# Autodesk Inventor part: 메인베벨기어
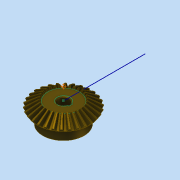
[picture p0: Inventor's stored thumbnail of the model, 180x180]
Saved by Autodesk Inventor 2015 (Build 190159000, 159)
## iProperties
Created: 2018-09
Part Number: 메인베벨기어
Material: 강철, 탄소
Document SubType Name: Modeling
Categories: <?xml version="1.0" encoding="UTF-16"?> <MemberInstance><Categories><FamilyTemplate><FamilyTemplateParameter ValueType="xs:double" Id="1" ObjectReferenceKey="da
Mass: 290.333 g
Surface Area: 107.709 cm^2
Volume: 36.8911 cm^3
Density: 7.87 g/cm^3
Appearance: 얼룩무늬
CustomPartVersion: 1
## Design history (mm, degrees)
node "맨 위 점"
node "메쉬 평면2"
sketch "톱니 본체 스케치"
  geometry: L1 (0, 0)-(28.669, -21.997); L2 (28.669, -21.997)-(31.109, -18.336); L3 (31.109, -18.336)-(0, 0); L4 (30, -20)-(0, 0); L5 (17.219, -13.212)-(18.685, -11.013); L6 (28.669, -21.997)-(17.219, -13.212); L7 (31.109, -18.336)-(18.685, -11.013); L8 (0, -39.387)-(0, 6.564) reference; L9 (0, -20)-(31.109, -20)
  constraints: 16 end point, 4 point on line, 3 perpendicular, 2 collinear, 1 horizontal alignment, 1 vertical alignment
  dimensions: "d0" = 60 diameter of L4.start L8 (= da_de); "d1" = 57.33744 diameter of L1.end L8 (= da_dfe); "d2" = 62.2188 diameter of L2.end L8 (= da_dae); "d3" = 14.4 distance between parallel lines of L2 L5 (= da_b); "d4" = 18.3359 vertical distance of L2.end L1.start (= da_ve)
revolve "톱니 본체" sketch "톱니 본체 스케치" stored, may be unused: angle "d5" = 90 deg
node "시작점"
node "톱니 평면"
sketch "시작 스케치"
  geometry: L1 (0, -23.505)-(0, 10.645) reference; L2 (-0.709, -2.928)-(0.709, -2.928); A1 r 19.188 centre (-19.457, -7.014) between (-0.709, -2.928) and (-3.232, 3.229); A2 r 19.188 centre (19.457, -7.014) between (3.232, 3.229) and (0.709, -2.928); A3 r 57.403 centre (0, -54.083) between (3.232, 3.229) and (-3.232, 3.229); 1 further point
  constraints: 6 point on circle, 3 centre point, 3 symmetric about line, 2 end point, 1 coincident, 1 perpendicular, 1 other
  dimensions: "d7" = 19.18795 radius of A1 (= fd_rr); "d8" = 19.45712 horizontal distance of point (0, -54.083) A1.centre (= fd_x); "d9" = 47.06905 vertical distance of point (0, -54.083) A1.centre (= fd_y); "d57" = 57.40327 radius of A3 (= 0.5 x fd_dva + 0.3 x da_he); "d58" = 51.15527 distance from line of A3.centre L2 (= 0.5 x fd_dva - 1.12 x da_he)
node "끝점"
  node "끝 평면"
sketch "3D 스케치 오른쪽"
  node "Helical Curve Right" dims "d65" = 229.90621 (computed from da_dm, da_delta, da_beta), "d66" = 31.5, "d67" = 60 (= da_de), "d68" = -9.82794 (= -da_delta), "d69" = 8.10972 (computed from fd_loft, da_delta)
node "끝 평면 오른쪽"
sketch "끝 스케치 오른쪽"
  geometry: L1 (0, -41.54)-(0, 13.178) reference; L2 (-0.422, -1.69)-(0.422, -1.69); A1 r 11.427 centre (-11.587, -4.123) between (-0.422, -1.69) and (-1.925, 1.977); A2 r 11.427 centre (11.587, -4.123) between (1.925, 1.977) and (0.422, -1.69); A3 r 34.184 centre (0, -32.153) between (1.925, 1.977) and (-1.925, 1.977); 1 further point
  constraints: 6 point on circle, 3 centre point, 3 symmetric about line, 2 end point, 1 coincident, 1 perpendicular, 1 other
  dimensions: "d70" = 11.58699 horizontal distance of A3.centre A1.centre (computed from fd_x, fd_ratio); "d71" = 28.03028 vertical distance of point (0, -32.153) A1.centre (computed from fd_y, fd_ratio); "d72" = 11.4267 radius of A1 (computed from fd_rr, fd_ratio); "d73" = 30.46369 distance from line of point (0, -32.153) L2 (computed from d58, fd_ratio); "d74" = 34.18446 radius of A3 (computed from d57, fd_ratio)
feature "로프트 오른쪽" sketch "끝 스케치 오른쪽" dims "d75" = 0, "d77" = 0, "d79" = 0, "d80" = 90 deg, "d85" = 20, "d92" = 90 deg, "d93" = 90 deg, "da_teethtype" = 0 [user parameter]
sketch "3D 스케치 왼쪽"
  node "Helical Curve Left" dims "d26" = 229.90621 (computed from da_dm, da_delta, da_beta), "d27" = 8.10972 (computed from fd_loft, da_delta), "d28" = 60 (= da_de), "d29" = -9.82794 (= -da_delta)
node "끝 평면 왼쪽"
sketch "끝 스케치 왼쪽" dims "d56" = 10.3728 (derived)
  geometry: L1 (0, -43.753)-(0, 15.405) reference; L2 (-0.422, -1.678)-(0.422, -1.678); A1 r 11.427 centre (-11.587, -4.111) between (-0.422, -1.678) and (-1.925, 1.988); A2 r 11.427 centre (11.587, -4.111) between (1.925, 1.988) and (0.422, -1.678); A3 r 34.184 centre (0, -32.142) between (1.925, 1.988) and (-1.925, 1.988); 2 further points; 1 other entity
  constraints: 6 point on circle, 3 centre point, 3 symmetric about line, 2 end point, 1 coincident, 2 other
  dimensions: "d30" = 11.4267 radius of A1 (computed from fd_rr, fd_ratio); "d31" = 11.58699 horizontal distance of point (0, -32.142) A1.centre (computed from fd_x, fd_ratio); "d32" = 28.03028 vertical distance of A1.centre point (0, -32.142) (computed from fd_y, fd_ratio); "d61" = 34.18446 radius of A3 (computed from d57, fd_ratio); "d62" = 30.46369 distance from line of point (0, -32.142) L2 (computed from d58, fd_ratio)
feature "로프트 왼쪽" sketch "끝 스케치 왼쪽" dims "d35" = 0, "d37" = 0, "d39" = 0, "d40" = 90 deg, "d84" = 10, "d90" = 90 deg, "d91" = 90 deg, "da_teethtype" = 0 [user parameter]
sketch "본체 스케치"
  geometry: L1 (0, -35.038)-(0, -19.531) reference; L2 (28.669, -21.997)-(17.219, -13.212) reference; L3 (17.219, -13.212)-(0, -13.212); L4 (28.669, -21.997)-(0, -21.997)
  constraints: 4 end point, 2 perpendicular, 2 point on line
revolve "본체 고정" sketch "본체 스케치" stored, may be unused: angle "d46" = 90 deg
feature "피치 지름" dims angle "d47" = 90 deg
sketch "스케치8"
  geometry: C1 r 22.5 at (0, 0); 1 further point
  constraints: 1 centre point, 1 coincident
  dimensions: "d94" = 45 diameter of C1
extrude "돌출1" join sketch "스케치8" distance "d95" = 13; taper "d96" = 0 deg
sketch "스케치9"
  geometry: 1 further point
hole "구멍1" sketch "스케치9" at (0, 0) diameter "d97" = 12; stored, may be unused: countersink angle "d101" = 90 deg, drill point angle "d103" = 118 deg; dims "d98" = 6, "d99" = 4, "d100" = 2, "d102" = 8
sketch "스케치10"
  geometry: L1 (5.657, 2)-(7.8, 2); L2 (7.8, 2)-(7.8, -2); L3 (7.8, -2)-(5.657, -2); A1 r 6 centre (0, 0) between (5.657, 2) and (5.657, -2) reference; 1 further point
  constraints: 6 end point, 2 parallel, 2 point on circle, 1 horizontal, 1 perpendicular
  dimensions: "d104" = 4 distance of L1.end L2.end; "d112" = 13.8 dimension on A1 L2
extrude "돌출2" cut sketch "스케치10" stored distance "d106" = 10; taper "d107" = 0 deg
chamfer "모따기1" distance "d108" = 1; stored, may be unused: second distance "d109" = 2, angle "d110" = 45 deg
fillet "모깎기1" dims "d111" = 2
sketch "스케치11"
  geometry: L1 (6.708, 2)-(7.8, 2) reference; L2 (7.8, 2)-(7.8, -2) reference; L3 (7.8, -2)-(6.708, -2) reference; L4 (0, 0)-(0, 89.049); A1 r 7 centre (0, 0) between (6.708, 2) and (6.708, -2) reference; A2 r 17.219 centre (0, 0) between (0.487, 17.212) and (-0.487, 17.212) reference; A3 r 17.219 centre (0, 0) between (-0.487, 17.212) and (-3.102, 16.937) reference; A4 r 17.219 centre (0, 0) between (-3.102, 16.937) and (-4.055, 16.735) reference; A5 r 17.219 centre (0, 0) between (-4.055, 16.735) and (-6.556, 15.922) reference; A6 r 17.219 centre (0, 0) between (-6.556, 15.922) and (-7.446, 15.526) reference; A7 r 17.219 centre (0, 0) between (-7.446, 15.526) and (-9.723, 14.211) reference; A8 r 17.219 centre (0, 0) between (-9.723, 14.211) and (-10.511, 13.639) reference; A9 r 17.219 centre (0, 0) between (-10.511, 13.639) and (-12.465, 11.879) reference; A10 r 17.219 centre (0, 0) between (-12.465, 11.879) and (-13.117, 11.155) reference; A11 r 17.219 centre (0, 0) between (-13.117, 11.155) and (-14.663, 9.028) reference; A12 r 17.219 centre (0, 0) between (-14.663, 9.028) and (-15.15, 8.184) reference; A13 r 17.219 centre (0, 0) between (-15.15, 8.184) and (-16.219, 5.782) reference; A14 r 17.219 centre (0, 0) between (-16.219, 5.782) and (-16.52, 4.856) reference; A15 r 17.219 centre (0, 0) between (-16.52, 4.856) and (-17.067, 2.284) reference; A16 r 17.219 centre (0, 0) between (-17.067, 2.284) and (-17.169, 1.315) reference; A17 r 17.219 centre (0, 0) between (-17.169, 1.315) and (-17.169, -1.315) reference; A18 r 17.219 centre (0, 0) between (-17.169, -1.315) and (-17.067, -2.284) reference; A19 r 17.219 centre (0, 0) between (-17.067, -2.284) and (-16.52, -4.856) reference; A20 r 17.219 centre (0, 0) between (-16.52, -4.856) and (-16.219, -5.782) reference; A21 r 17.219 centre (0, 0) between (-16.219, -5.782) and (-15.15, -8.184) reference; A22 r 17.219 centre (0, 0) between (-15.15, -8.184) and (-14.663, -9.028) reference; A23 r 17.219 centre (0, 0) between (-14.663, -9.028) and (-13.117, -11.155) reference; A24 r 17.219 centre (0, 0) between (-13.117, -11.155) and (-12.465, -11.879) reference; A25 r 17.219 centre (0, 0) between (-12.465, -11.879) and (-10.511, -13.639) reference; A26 r 17.219 centre (0, 0) between (-10.511, -13.639) and (-9.723, -14.211) reference; A27 r 17.219 centre (0, 0) between (-9.723, -14.211) and (-7.446, -15.526) reference; A28 r 17.219 centre (0, 0) between (-7.446, -15.526) and (-6.556, -15.922) reference; A29 r 17.219 centre (0, 0) between (-6.556, -15.922) and (-4.055, -16.735) reference; A30 r 17.219 centre (0, 0) between (-4.055, -16.735) and (-3.102, -16.937) reference; A31 r 17.219 centre (0, 0) between (-3.102, -16.937) and (-0.487, -17.212) reference; A32 r 17.219 centre (0, 0) between (-0.487, -17.212) and (0.487, -17.212) reference; A33 r 17.219 centre (0, 0) between (0.487, -17.212) and (3.102, -16.937) reference; A34 r 17.219 centre (0, 0) between (3.102, -16.937) and (4.055, -16.735) reference; A35 r 17.219 centre (0, 0) between (4.055, -16.735) and (6.556, -15.922) reference; A36 r 17.219 centre (0, 0) between (6.556, -15.922) and (7.446, -15.526) reference; A37 r 17.219 centre (0, 0) between (7.446, -15.526) and (9.723, -14.211) reference; A38 r 17.219 centre (0, 0) between (9.723, -14.211) and (10.511, -13.639) reference; A39 r 17.219 centre (0, 0) between (10.511, -13.639) and (12.465, -11.879) reference; A40 r 17.219 centre (0, 0) between (12.465, -11.879) and (13.117, -11.155) reference; A41 r 17.219 centre (0, 0) between (13.117, -11.155) and (14.663, -9.028) reference; A42 r 17.219 centre (0, 0) between (14.663, -9.028) and (15.15, -8.184) reference; A43 r 17.219 centre (0, 0) between (15.15, -8.184) and (16.219, -5.782) reference; A44 r 17.219 centre (0, 0) between (16.219, -5.782) and (16.52, -4.856) reference; A45 r 17.219 centre (0, 0) between (16.52, -4.856) and (17.067, -2.284) reference; A46 r 17.219 centre (0, 0) between (17.067, -2.284) and (17.169, -1.315) reference; A47 r 17.219 centre (0, 0) between (17.169, -1.315) and (17.169, 1.315) reference; A48 r 17.219 centre (0, 0) between (17.169, 1.315) and (17.067, 2.284) reference; A49 r 17.219 centre (0, 0) between (17.067, 2.284) and (16.52, 4.856) reference; A50 r 17.219 centre (0, 0) between (16.52, 4.856) and (16.219, 5.782) reference; A51 r 17.219 centre (0, 0) between (16.219, 5.782) and (15.15, 8.184) reference; A52 r 17.219 centre (0, 0) between (15.15, 8.184) and (14.663, 9.028) reference; A53 r 17.219 centre (0, 0) between (14.663, 9.028) and (13.117, 11.155) reference; A54 r 17.219 centre (0, 0) between (13.117, 11.155) and (12.465, 11.879) reference; A55 r 17.219 centre (0, 0) between (12.465, 11.879) and (10.511, 13.639) reference; A56 r 17.219 centre (0, 0) between (10.511, 13.639) and (9.723, 14.211) reference; A57 r 17.219 centre (0, 0) between (9.723, 14.211) and (7.446, 15.526) reference; A58 r 17.219 centre (0, 0) between (7.446, 15.526) and (6.556, 15.922) reference; A59 r 17.219 centre (0, 0) between (6.556, 15.922) and (4.055, 16.735) reference; A60 r 17.219 centre (0, 0) between (4.055, 16.735) and (3.102, 16.937) reference; A61 r 17.219 centre (0, 0) between (3.102, 16.937) and (0.487, 17.212) reference
  constraints: 2 end point, 1 vertical
body "Solid1"
feature "로프트" dims "d17" = 0, "d18" = 90 deg, "d19" = 0, "d20" = 90 deg, "d89" = 0, "da_teethtype" = 0 [user parameter]
pattern_circular "원형 패턴" dims angle "d22" = 360 deg, "d88" = 0, "da_teethtype" = 0 [user parameter]
pattern_circular "원형 패턴 오른쪽" dims angle "d82" = 360 deg, "da_teethtype" = 0 [user parameter]
pattern_circular "원형 패턴 왼쪽" dims angle "d42" = 360 deg, "da_teethtype" = 0 [user parameter]
sketch "끝 스케치"
  geometry: L1 (0, -15.359)-(0, 6.983) reference; L2 (-0.422, -1.69)-(0.422, -1.69); A1 r 11.427 centre (-11.587, -4.123) between (-0.422, -1.69) and (-1.925, 1.977); A2 r 11.427 centre (11.587, -4.123) between (1.925, 1.977) and (0.422, -1.69); A3 r 34.184 centre (0, -32.153) between (1.925, 1.977) and (-1.925, 1.977); 1 further point
  constraints: 6 point on circle, 3 centre point, 3 symmetric about line, 2 end point, 1 coincident, 1 other
  dimensions: "d12" = 11.4267 radius of A1 (computed from fd_rr, fd_ratio); "d15" = 11.58699 horizontal distance of A1.centre point (0, -32.153) (computed from fd_x, fd_ratio); "d16" = 28.03028 vertical distance of A1.centre point (0, -32.153) (computed from fd_y, fd_ratio); "d59" = 34.18446 radius of A3 (computed from d57, fd_ratio); "d60" = 30.46369 distance from line of A3.centre L2 (computed from d58, fd_ratio)
sketch "Sketch6"
  geometry: L1 (30, -20)-(0, 0) reference; L2 (0, -37.8)-(0, 6.3) reference
body "Srf1"
other parameters: "da_b" = 14.4 [user parameter; used in 2 equation terms], "da_de" = 60 [user parameter; used in 4 equation terms], "da_dae" = 62.2188 [user parameter; used in 2 equation terms], "da_dfe" = 57.33744 [user parameter; used in 1 equation term], "da_le" = 36.05551 [user parameter; used in 1 equation term], "da_omega" = 90 deg [user parameter; used in 1 equation term], "da_beta" = 0 [user parameter; used in 2 equation terms], "da_delta" = 9.82794 [user parameter; used in 8 equation terms], "da_alpha" = 20 deg [user parameter; used in 2 equation terms], "da_he" = 4.4 [user parameter; used in 4 equation terms], "da_ve" = 18.3359 [user parameter; used in 1 equation term], "fd_dv" = 108.16654 (computed from da_de, da_delta) [user parameter; used in 1 equation term], "fd_dva" = 112.16654 (computed from da_dae, da_delta) [user parameter; used in 3 equation terms], "fd_dvb" = 101.6433 (computed from fd_dv, da_alpha) [user parameter; used in 2 equation terms], "da_zv" = 540.83269 [user parameter; used in 1 equation term], "fd_loft" = 14.62 (= da_b + 0.05 x da_he) [user parameter; used in 4 equation terms], "fd_ratio" = 5.95514 (computed from da_le, fd_loft) [user parameter; used in 15 equation terms], "fd_rr" = 19.18795 (computed from fd_dd, fd_dvb) [user parameter; used in 6 equation terms], "fd_angle" = 0.29367 (computed from da_zv) [user parameter; used in 4 equation terms], "fd_x1" = 1.58802 (computed from da_dvw, fd_angle) [user parameter; used in 1 equation term], "fd_y1" = 54.05995 (computed from da_dvw, fd_angle) [user parameter; used in 1 equation term], "fd_x2" = 17.8691 (computed from fd_rr, fd_angle2, fd_angle) [user parameter; used in 1 equation term], "fd_y2" = 6.9909 (computed from fd_rr, fd_angle2, fd_angle) [user parameter; used in 1 equation term], "fd_x" = 19.45712 (= fd_x1 + fd_x2) [user parameter; used in 4 equation terms], "fd_y" = 47.06905 (= fd_y1 - fd_y2) [user parameter; used in 4 equation terms], "fd_angle2" = 3.43555 (computed from fd_dvb, fd_dd, da_alpha) [user parameter; used in 2 equation terms], "fd_dd" = 108.64654 (= fd_dva - 0.8 x da_he) [user parameter; used in 2 equation terms], "da_dvw" = 108.16654 [user parameter; used in 2 equation terms], "d11" = 14.62 (= fd_loft), "da_dm" = 48.01848 [user parameter; used in 2 equation terms], "da_x" = 0 [user parameter], "da_m" = 2 [user parameter], "d48" = 0, "d49" = 0, "d50" = 90 deg (= da_omega), "d51" = 6 deg (computed from da_z), "d52" = 0, "d53" = 0, "d54" = 0
